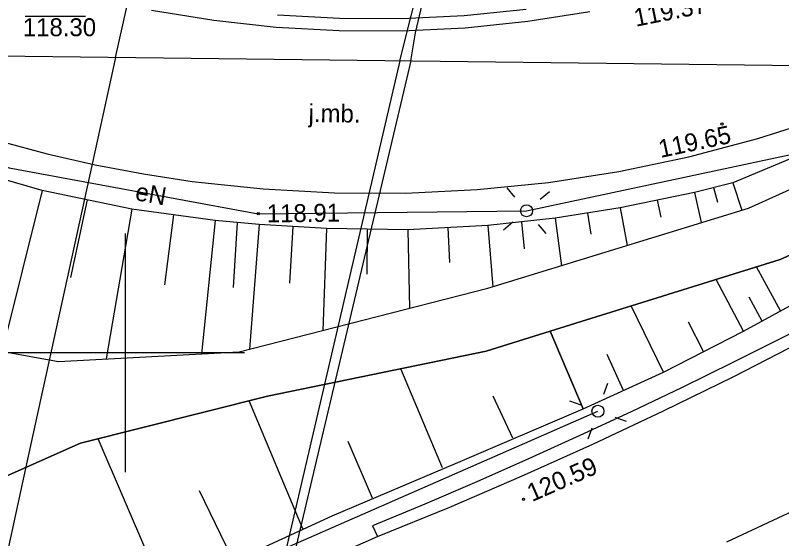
# Model space of a CAD drawing. Extents: x 6424617 to 6425697, y 5665845 to 5667190.
# Drawn here: x 6425495.41 to 6425527.49, y 5666792.22 to 5666814.14 of the extents above; entities that cross this region are included whole.
import ezdxf

# ---------------------------------------------------------------- set-up
doc = ezdxf.new("R2010")
doc.units = 0
for name, color, linetype in [('Warstwa 10', 7, 'Continuous'), ('Warstwa 12', 7, 'Continuous'), ('Warstwa 13', 7, 'Continuous'), ('Warstwa 14', 7, 'Continuous'), ('Warstwa 2', 7, 'Continuous'), ('Warstwa 20', 7, 'Continuous'), ('Warstwa 21', 7, 'Continuous'), ('Warstwa 25', 7, 'Continuous'), ('Warstwa 4', 7, 'Continuous'), ('Warstwa 6', 7, 'Continuous'), ('Warstwa 63', 7, 'Continuous'), ('Warstwa 8', 7, 'Continuous'), ('Warstwa 9', 7, 'Continuous')]:
    doc.layers.add(name, color=color, linetype=linetype)

msp = doc.modelspace()

# ---------------------------------------------------------------- linework, layer by layer
at = {"layer": 'Warstwa 10'}
for points in [[(6425511.502, 5666812.229), (6425512.943, 5666817.949)], [(6425511.502, 5666812.229), (6425505.347, 5666785.804), (6425490.939, 5666726.925), (6425483.148, 5666695.285), (6425465.075, 5666699.074), (6425463.492, 5666694.538), (6425461.289, 5666683.928), (6425457.56, 5666668.611), (6425452.397, 5666649.025), (6425443.501, 5666614.107), (6425444.454, 5666609.948), (6425442.828, 5666607.233), (6425442.381, 5666606.077), (6425439.907, 5666599.491), (6425438.985, 5666589.841), (6425438.533, 5666586.618), (6425438.687, 5666584.707), (6425442.314, 5666582.223), (6425462.873, 5666574.552), (6425461.354, 5666569.137), (6425473.214, 5666563.224), (6425473.065, 5666562.687)]]:
    msp.add_lwpolyline(points, dxfattribs=at)
at = {"layer": 'Warstwa 12'}
for points in [[(6425499.608, 5666812.372), (6425501.312, 5666820.03), (6425502.717, 5666826.643), (6425504.653, 5666835.914), (6425506.015, 5666841.883), (6425506.579, 5666844.134), (6425507.337, 5666847.688), (6425511.705, 5666865.996), (6425515.14, 5666880.945), (6425517.137, 5666889.164), (6425519.622, 5666899.265), (6425524.222, 5666918.678), (6425526.588, 5666928.262), (6425527.475, 5666931.839)], [(6425511.969, 5666812.223), (6425512.165, 5666813.402), (6425513.737, 5666820.109)], [(6425499.608, 5666812.372), (6425495.95, 5666795.671), (6425486.186, 5666750.745), (6425486.2, 5666750.424), (6425485.09, 5666746.715), (6425483.809, 5666741.562), (6425478.514, 5666721.742), (6425475.138, 5666709.091), (6425474.202, 5666705.85), (6425473.405, 5666702.579), (6425462.582, 5666662.473), (6425462.296, 5666661.501), (6425462.173, 5666661.094)], [(6425483.301, 5666812.571), (6425486.24, 5666810.85), (6425495.15, 5666807.75), (6425505.58, 5666805.83), (6425516.81, 5666805.95), (6425530.63, 5666808.89), (6425537.196, 5666811.92)], [(6425511.969, 5666812.223), (6425503.565, 5666776.699), (6425494.804, 5666740.869), (6425483.613, 5666695.097), (6425483.148, 5666695.285), (6425465.075, 5666699.074), (6425463.492, 5666694.538), (6425461.289, 5666683.928), (6425457.56, 5666668.611), (6425452.397, 5666649.025), (6425443.501, 5666614.107), (6425444.454, 5666609.948), (6425442.828, 5666607.233), (6425439.907, 5666599.491), (6425438.985, 5666589.841), (6425438.533, 5666586.618), (6425438.687, 5666584.707), (6425442.314, 5666582.223), (6425462.873, 5666574.552), (6425463.208, 5666574.431), (6425461.755, 5666569.388), (6425473.557, 5666563.362), (6425473.425, 5666562.682)], [(6425421.88, 5666719.91), (6425423.54, 5666722.99), (6425426.42, 5666727.86), (6425430.52, 5666733.86), (6425437.51, 5666743.03), (6425446.31, 5666752.86), (6425455.45, 5666761.23), (6425465.09, 5666768.89), (6425475.88, 5666776.36), (6425486.03, 5666782.02), (6425494, 5666786.05), (6425505.21, 5666791.17), (6425519.8, 5666797.56)]]:
    msp.add_lwpolyline(points, dxfattribs=at)
at = {"layer": 'Warstwa 14'}
msp.add_line((6425498.347, 5666814.088), (6425495.823, 5666814.088), dxfattribs=at)
msp.add_circle((6425505.58, 5666805.83), 0.045, dxfattribs=at)
at = {"layer": 'Warstwa 2'}
for centre in [(6425516.81, 5666805.95), (6425519.8, 5666797.56)]:
    msp.add_circle(centre, 0.25, dxfattribs=at)
at = {"layer": 'Warstwa 20'}
for points in [[(6425536.954, 5666811.923), (6425525.448, 5666807.124), (6425523.838, 5666806.716), (6425520.732, 5666806.071), (6425518.007, 5666805.646), (6425515.187, 5666805.341), (6425511.846, 5666805.15), (6425508.44, 5666805.208), (6425505.612, 5666805.37), (6425503.771, 5666805.545), (6425500.287, 5666806.012), (6425496.536, 5666806.804), (6425493.577, 5666807.654), (6425490.89, 5666808.515), (6425488.443, 5666809.424), (6425485.396, 5666810.743), (6425481.867, 5666812.588)], [(6425490.445, 5666784.582), (6425496.465, 5666787.566), (6425502.572, 5666790.371), (6425508.678, 5666793.175), (6425513.932, 5666795.414), (6425519.185, 5666797.654), (6425522.542, 5666799.198), (6425525.894, 5666800.914), (6425530.546, 5666803.444), (6425533.553, 5666805.256), (6425538.799, 5666808.775), (6425542.115, 5666811.215), (6425542.931, 5666811.851)]]:
    msp.add_lwpolyline(points, dxfattribs=at)
at = {"layer": 'Warstwa 21'}
for points in [[(6425468.392, 5666812.751), (6425469.664, 5666811.753), (6425475.779, 5666807.481), (6425482.248, 5666803.463), (6425489.746, 5666800.997), (6425497.214, 5666799.642), (6425504.774, 5666800.045), (6425515.195, 5666802.708), (6425526.109, 5666806.062), (6425536.154, 5666810.592), (6425538.289, 5666811.907)], [(6425422.574, 5666722.304), (6425431.815, 5666741.584), (6425441.056, 5666760.863), (6425453.143, 5666770.998), (6425464.372, 5666779.068), (6425474.879, 5666784.82), (6425481.549, 5666788.4), (6425486.475, 5666791.043), (6425498.143, 5666796.224), (6425505.971, 5666798.183), (6425515.118, 5666800.069), (6425517.803, 5666800.908), (6425527.431, 5666803.918), (6425535.771, 5666807.678), (6425542.544, 5666811.856)]]:
    msp.add_lwpolyline(points, dxfattribs=at)
at = {"layer": 'Warstwa 25'}
for centre in [(6425524.992, 5666809.583), (6425516.686, 5666793.868)]:
    msp.add_circle(centre, 0.045, dxfattribs=at)
at = {"layer": 'Warstwa 4'}
for points in [[(6425516.328, 5666806.524), (6425516.006, 5666806.907)], [(6425517.384, 5666806.432), (6425517.767, 5666806.754)], [(6425516.236, 5666805.468), (6425515.853, 5666805.146)], [(6425517.292, 5666805.376), (6425517.614, 5666804.993)], [(6425520.05, 5666798.267), (6425520.217, 5666798.738)], [(6425519.093, 5666797.81), (6425518.622, 5666797.977)], [(6425520.507, 5666797.31), (6425520.978, 5666797.143)], [(6425519.55, 5666796.853), (6425519.383, 5666796.382)]]:
    msp.add_lwpolyline(points, dxfattribs=at)
at = {"layer": 'Warstwa 6'}
for points in [[(6425516.799, 5666814.385), (6425514.202, 5666814.12), (6425511.595, 5666813.991), (6425508.985, 5666813.997), (6425506.379, 5666814.14)], [(6425545.562, 5666811.819), (6425545.153, 5666811.5), (6425543.516, 5666810.291), (6425541.856, 5666809.113), (6425540.175, 5666807.965), (6425538.473, 5666806.849), (6425536.751, 5666805.764), (6425535.009, 5666804.711), (6425533.249, 5666803.69), (6425531.469, 5666802.701), (6425529.672, 5666801.746), (6425527.569, 5666800.661), (6425525.454, 5666799.597), (6425523.329, 5666798.555), (6425521.193, 5666797.535), (6425519.047, 5666796.536), (6425516.891, 5666795.559), (6425514.725, 5666794.605), (6425512.549, 5666793.673), (6425510.364, 5666792.762), (6425510.566, 5666792.308)]]:
    msp.add_lwpolyline(points, dxfattribs=at)
at = {"layer": 'Warstwa 63'}
for p, q in [((6425500, 5666805), (6425500, 5666795)), ((6425505, 5666800), (6425495, 5666800))]:
    msp.add_line(p, q, dxfattribs=at)
at = {"layer": 'Warstwa 8'}
for p, q in [((6425501.112, 5666814.347), (6425503.714, 5666813.929)), ((6425516.859, 5666813.885), (6425519.464, 5666814.289)), ((6425503.714, 5666813.929), (6425506.335, 5666813.645)), ((6425506.335, 5666813.645), (6425508.967, 5666813.498)), ((6425511.603, 5666813.489), (6425514.236, 5666813.618)), ((6425514.236, 5666813.618), (6425516.859, 5666813.885)), ((6425508.967, 5666813.498), (6425511.603, 5666813.489)), ((6425485.159, 5666812.548), (6425534.463, 5666811.953)), ((6425485.159, 5666812.548), (6425534.463, 5666811.953)), ((6425526.501, 5666808.973), (6425529.349, 5666809.885)), ((6425494.755, 5666808.862), (6425496.745, 5666808.334)), ((6425523.609, 5666808.21), (6425526.501, 5666808.973)), ((6425496.745, 5666808.334), (6425498.753, 5666807.878)), ((6425520.681, 5666807.599), (6425523.609, 5666808.21)), ((6425498.753, 5666807.878), (6425500.776, 5666807.494)), ((6425517.726, 5666807.142), (6425520.681, 5666807.599)), ((6425500.776, 5666807.494), (6425502.812, 5666807.183)), ((6425502.812, 5666807.183), (6425505.786, 5666806.864)), ((6425505.786, 5666806.864), (6425508.772, 5666806.7)), ((6425514.75, 5666806.839), (6425517.726, 5666807.142)), ((6425508.772, 5666806.7), (6425511.763, 5666806.691)), ((6425511.763, 5666806.691), (6425514.75, 5666806.839)), ((6425525.485, 5666799.018), (6425528.396, 5666800.513)), ((6425522.549, 5666797.573), (6425525.485, 5666799.018)), ((6425519.587, 5666796.18), (6425522.549, 5666797.573)), ((6425516.603, 5666794.837), (6425519.587, 5666796.18)), ((6425513.595, 5666793.547), (6425516.603, 5666794.837)), ((6425510.566, 5666792.308), (6425513.595, 5666793.547)), ((6425525.197, 5666792.09), (6425528.218, 5666793.499)), ((6425506.912, 5666790.714), (6425510.566, 5666792.308))]:
    msp.add_line(p, q, dxfattribs=at)
at = {"layer": 'Warstwa 9'}
for p, q in [((6425524.643, 5666806.92), (6425524.812, 5666806.318)), ((6425525.448, 5666807.124), (6425525.831, 5666805.976)), ((6425496.536, 5666806.804), (6425494.858, 5666800.07)), ((6425523.838, 5666806.716), (6425524.129, 5666805.454)), ((6425498.412, 5666806.408), (6425497.722, 5666803.158)), ((6425522.285, 5666806.394), (6425522.429, 5666805.685)), ((6425500.287, 5666806.012), (6425499.207, 5666799.748)), ((6425520.732, 5666806.071), (6425521.018, 5666804.498)), ((6425502.029, 5666805.778), (6425501.66, 5666802.855)), ((6425518.007, 5666805.646), (6425518.27, 5666803.653)), ((6425519.37, 5666805.858), (6425519.507, 5666804.967)), ((6425503.771, 5666805.545), (6425503.206, 5666799.961)), ((6425504.692, 5666805.458), (6425504.531, 5666802.744)), ((6425505.612, 5666805.37), (6425505.215, 5666800.158)), ((6425507.026, 5666805.289), (6425506.887, 5666802.919)), ((6425515.187, 5666805.341), (6425515.398, 5666802.771)), ((6425516.597, 5666805.494), (6425516.716, 5666804.353)), ((6425508.44, 5666805.208), (6425508.282, 5666800.941)), ((6425510.143, 5666805.179), (6425510.12, 5666803.292)), ((6425511.846, 5666805.15), (6425511.912, 5666801.869)), ((6425513.516, 5666805.246), (6425513.586, 5666803.783)), ((6425527.445, 5666801.757), (6425526.44, 5666803.608)), ((6425525.894, 5666800.914), (6425524.75, 5666803.08)), ((6425526.67, 5666801.336), (6425526.132, 5666802.34)), ((6425522.542, 5666799.198), (6425521.197, 5666801.969)), ((6425524.218, 5666800.056), (6425523.596, 5666801.29)), ((6425519.185, 5666797.654), (6425517.803, 5666800.908)), ((6425517.803, 5666800.908), (6425519.185, 5666797.654)), ((6425520.864, 5666798.426), (6425520.182, 5666799.932)), ((6425513.299, 5666795.183), (6425511.547, 5666799.333)), ((6425507.448, 5666792.63), (6425505.202, 5666797.99)), ((6425516.238, 5666796.429), (6425515.415, 5666798.195)), ((6425501.634, 5666789.994), (6425498.877, 5666796.408)), ((6425510.369, 5666793.917), (6425509.345, 5666796.292)), ((6425504.537, 5666791.322), (6425503.121, 5666794.219))]:
    msp.add_line(p, q, dxfattribs=at)
for points in [[(6425490.445, 5666784.582), (6425496.465, 5666787.566), (6425502.572, 5666790.371), (6425508.678, 5666793.175), (6425513.932, 5666795.414), (6425519.185, 5666797.654), (6425522.542, 5666799.198), (6425525.894, 5666800.914), (6425530.546, 5666803.444), (6425533.553, 5666805.256), (6425538.799, 5666808.775), (6425542.115, 5666811.215), (6425542.931, 5666811.851), (6425542.544, 5666811.856), (6425535.771, 5666807.678), (6425527.431, 5666803.918), (6425517.803, 5666800.908), (6425515.118, 5666800.069), (6425505.971, 5666798.183), (6425498.143, 5666796.224), (6425486.475, 5666791.043)], [(6425489.746, 5666800.997), (6425497.214, 5666799.642), (6425504.774, 5666800.045), (6425515.195, 5666802.708), (6425526.109, 5666806.062), (6425536.154, 5666810.592), (6425538.289, 5666811.907), (6425536.954, 5666811.923), (6425525.448, 5666807.124), (6425523.838, 5666806.716), (6425520.732, 5666806.071), (6425518.007, 5666805.646), (6425515.187, 5666805.341), (6425511.846, 5666805.15), (6425508.44, 5666805.208), (6425505.612, 5666805.37), (6425503.771, 5666805.545), (6425500.287, 5666806.012), (6425496.536, 5666806.804), (6425493.577, 5666807.654)]]:
    msp.add_lwpolyline(points, dxfattribs=at)

# ---------------------------------------------------------------- texts
at = {"layer": 'Warstwa 13'}
msp.add_text('eN', height=0.75, rotation=349.5673, dxfattribs=at).set_placement((6425500.39, 5666806.404))
at = {"layer": 'Warstwa 14'}
msp.add_text('118.30', height=0.75, dxfattribs=at).set_placement((6425495.722, 5666813.262))
msp.add_text('118.91', height=0.75, rotation=0.6131, dxfattribs=at).set_placement((6425505.938, 5666805.464))
at = {"layer": 'Warstwa 25'}
for s, rotation, p in [('119.37', 11.3331, (6425521.39, 5666813.654)), ('119.65', 12.0092, (6425522.423, 5666808.162)), ('120.59', 23.6517, (6425517.042, 5666793.753))]:
    msp.add_text(s, height=0.75, rotation=rotation, dxfattribs=at).set_placement(p)
at = {"layer": 'Warstwa 8'}
msp.add_text('j.mb.', height=0.75, rotation=359.3076, dxfattribs=at).set_placement((6425507.682, 5666809.668))

doc.saveas('drawing.dxf')
